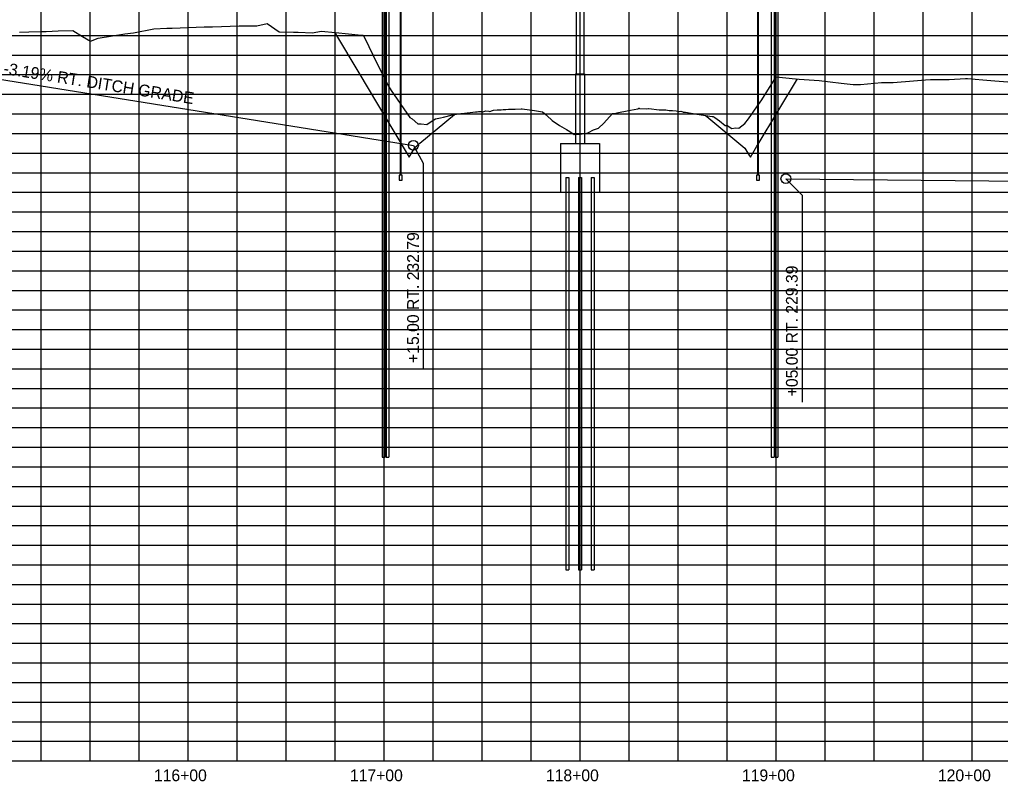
# Model space of a CAD drawing. Extents: x 921603 to 924670, y 1759276 to 1766491.
# Drawn here: x 923154 to 923654, y 1764922 to 1765310 of the extents above; entities that cross this region are included whole.
import ezdxf

# ---------------------------------------------------------------- set-up
doc = ezdxf.new("R2010")
doc.units = 0
for name, color, linetype in [('B-Gen-Hidden', 7, 'Continuous'), ('B-Gen-Object', 7, 'Continuous'), ('B-Sub-Retaining Wall', 7, 'Continuous'), ('R_Axis_Annotation', 7, 'Continuous'), ('R_Exist Surface', 7, 'Continuous'), ('R_Grid', 7, 'Continuous'), ('R_Grid_Minor', 7, 'Continuous'), ('R_Prop Surface', 7, 'Continuous'), ('R_Vert Alg', 7, 'Continuous'), ('R_Vert Alg Annot', 7, 'Continuous')]:
    doc.layers.add(name, color=color, linetype=linetype)

msp = doc.modelspace()

# ---------------------------------------------------------------- linework, layer by layer
at = {"layer": 'B-Gen-Hidden'}
for p, q in [((923338.85, 1765337.18), (923338.85, 1765087.18)), ((923340.35, 1765337.18), (923340.35, 1765087.18)), ((923340.85, 1765337.18), (923340.85, 1765087.18)), ((923342.35, 1765337.18), (923342.35, 1765087.18)), ((923537.3, 1765337.18), (923537.3, 1765087.18)), ((923538.8, 1765337.18), (923538.8, 1765087.18)), ((923539.3, 1765337.18), (923539.3, 1765087.18)), ((923540.8, 1765337.18), (923540.8, 1765087.18)), ((923437.58, 1765257.21), (923437.58, 1765247.23)), ((923442.08, 1765257.69), (923442.08, 1765247.23)), ((923429.83, 1765247.23), (923449.83, 1765247.23)), ((923429.83, 1765247.23), (923429.83, 1765222.23)), ((923449.83, 1765247.23), (923449.83, 1765222.23)), ((923432.58, 1765229.73), (923432.58, 1765029.73)), ((923432.58, 1765229.73), (923434.08, 1765229.73)), ((923434.08, 1765229.73), (923434.08, 1765029.73)), ((923439.08, 1765229.73), (923439.08, 1765029.73)), ((923439.08, 1765229.73), (923440.58, 1765229.73)), ((923440.58, 1765229.73), (923440.58, 1765029.73)), ((923445.58, 1765229.73), (923445.58, 1765029.73)), ((923445.58, 1765229.73), (923447.08, 1765229.73)), ((923447.08, 1765229.73), (923447.08, 1765029.73)), ((923449.83, 1765222.23), (923429.83, 1765222.23)), ((923338.85, 1765087.18), (923340.35, 1765087.18)), ((923340.85, 1765087.18), (923342.35, 1765087.18)), ((923537.3, 1765087.18), (923538.8, 1765087.18)), ((923539.3, 1765087.18), (923540.8, 1765087.18)), ((923432.58, 1765029.73), (923434.08, 1765029.73)), ((923439.08, 1765029.73), (923440.58, 1765029.73)), ((923445.58, 1765029.73), (923447.08, 1765029.73))]:
    msp.add_line(p, q, dxfattribs=at)
at = {"layer": 'B-Gen-Object'}
for p, q in [((923437.83, 1765330.16), (923437.83, 1765282.66)), ((923441.84, 1765330.16), (923441.84, 1765282.66)), ((923437.58, 1765282.66), (923437.58, 1765257.21)), ((923437.58, 1765282.66), (923442.08, 1765282.66)), ((923442.08, 1765282.66), (923442.08, 1765257.69))]:
    msp.add_line(p, q, dxfattribs=at)
at = {"layer": 'B-Sub-Retaining Wall'}
for p, q in [((923348.02, 1765334.08), (923348.02, 1765230.99)), ((923348.52, 1765230.99), (923348.52, 1765334.08)), ((923530.4, 1765334.08), (923530.4, 1765230.99)), ((923530.9, 1765230.99), (923530.9, 1765334.08)), ((923347.54, 1765230.99), (923347.54, 1765228.49)), ((923349, 1765230.99), (923347.54, 1765230.99)), ((923349, 1765228.49), (923349, 1765230.99)), ((923529.92, 1765230.99), (923529.92, 1765228.49)), ((923531.38, 1765230.99), (923529.92, 1765230.99)), ((923531.38, 1765228.49), (923531.38, 1765230.99)), ((923347.54, 1765228.49), (923349, 1765228.49)), ((923529.92, 1765228.49), (923531.38, 1765228.49))]:
    msp.add_line(p, q, dxfattribs=at)
at = {"layer": 'R_Exist Surface'}
msp.add_lwpolyline([(923153.87, 1765303.95), (923158.57, 1765304.12), (923164.55, 1765304.24), (923167.47, 1765304.31), (923173.49, 1765304.53), (923181.06, 1765304.72), (923186.05, 1765301.75), (923190.01, 1765299.41), (923194.03, 1765300.92), (923207.55, 1765303.15), (923207.56, 1765303.15), (923212.09, 1765303.63), (923222.44, 1765305.62), (923229.05, 1765305.89), (923230.22, 1765305.93), (923231.8, 1765305.97), (923248.12, 1765306.6), (923250.55, 1765306.66), (923252.29, 1765306.7), (923265.93, 1765307.21), (923272.06, 1765307.16), (923274.92, 1765307.15), (923280.21, 1765308.4), (923286.34, 1765304.18), (923293.56, 1765303.91), (923294.54, 1765303.87), (923296.01, 1765303.89), (923303.3, 1765303.62), (923307.83, 1765304.46), (923315.06, 1765303.73), (923328.41, 1765302.38), (923329.1, 1765302.36), (923329.11, 1765302.35), (923329.84, 1765301.29), (923336.52, 1765287.44), (923336.56, 1765287.37), (923342.02, 1765276.41), (923343.53, 1765274.17), (923353.01, 1765260.44), (923354.21, 1765259.73), (923357.1, 1765257.12), (923358.06, 1765257.13), (923358.77, 1765257.13), (923361.68, 1765256.82), (923363.86, 1765258.42), (923366.05, 1765259.77), (923368.67, 1765260.28), (923370.13, 1765260.63), (923374.8, 1765261.72), (923375.68, 1765262.01), (923379, 1765262.43), (923379.56, 1765262.5), (923386.51, 1765263.27), (923387.36, 1765263.37), (923387.94, 1765263.48), (923389.79, 1765263.52), (923390.25, 1765263.38), (923391.25, 1765263.65), (923391.76, 1765263.74), (923393.21, 1765263.57), (923393.76, 1765263.5), (923395.08, 1765263.9), (923395.67, 1765264.16), (923397.59, 1765264.36), (923398.48, 1765264.38), (923399.67, 1765264.3), (923400.57, 1765264.52), (923401.06, 1765264.46), (923401.32, 1765264.43), (923401.93, 1765264.54), (923403.35, 1765264.71), (923404.11, 1765264.59), (923406.25, 1765264.59), (923406.76, 1765264.59), (923409.73, 1765264.81), (923410.36, 1765264.75), (923410.36, 1765264.75), (923416.62, 1765263.91), (923420.65, 1765263.23), (923422.57, 1765261.76), (923422.96, 1765261.46), (923425.62, 1765258.92), (923429.35, 1765256.4), (923432.88, 1765254.23), (923434.62, 1765253.23), (923436.86, 1765251.78), (923439.72, 1765251.92), (923443.26, 1765252.48), (923444.07, 1765252.84), (923446.72, 1765254.04), (923449.29, 1765255.02), (923452.02, 1765257.55), (923456.38, 1765262.53), (923458.31, 1765262.69), (923458.74, 1765262.74), (923459.49, 1765262.89), (923463.93, 1765263.81), (923465.57, 1765264.15), (923469.28, 1765264.91), (923469.87, 1765265.09), (923469.95, 1765265.1), (923470.17, 1765265.08), (923473.66, 1765264.83), (923473.79, 1765264.85), (923474.72, 1765264.96), (923474.92, 1765264.93), (923480.16, 1765264.28), (923480.35, 1765264.27), (923483.38, 1765264.28), (923483.54, 1765264.26), (923485.26, 1765263.98), (923485.51, 1765263.97), (923487.07, 1765263.9), (923488.94, 1765263.81), (923490.29, 1765263.48), (923490.36, 1765263.47), (923491.33, 1765263.57), (923492.3, 1765263.22), (923492.38, 1765263.21), (923493.7, 1765263.08), (923493.71, 1765263.08), (923499.44, 1765262.17), (923507.28, 1765260.94), (923507.82, 1765260.84), (923508.05, 1765260.7), (923508.57, 1765260.34), (923511.04, 1765258.67), (923513.95, 1765256.28), (923515.12, 1765256.27), (923515.99, 1765255.71), (923517.3, 1765254.75), (923519.09, 1765255.06), (923520.92, 1765255), (923523.85, 1765257.35), (923525.74, 1765259.69), (923530.07, 1765265.88), (923532.59, 1765269.49), (923539.92, 1765281.15), (923549.68, 1765280.06), (923551.58, 1765279.95), (923561.75, 1765279.36), (923573.08, 1765277.93), (923579.21, 1765277.16), (923582.85, 1765277.17), (923593.6, 1765278.21), (923594.58, 1765278.21), (923599.66, 1765278.22), (923610.02, 1765279.05), (923616.08, 1765279.54), (923618.61, 1765279.75), (923628.16, 1765279.72), (923636.41, 1765280.3), (923637.58, 1765280.22), (923645.31, 1765279.68), (923651.49, 1765279.08), (923660.29, 1765278.47)], dxfattribs=at)
at = {"layer": 'R_Grid'}
for p, q in [((923239.83, 1764932.26), (923239.83, 1765532.26)), ((923339.83, 1764932.26), (923339.83, 1765532.26)), ((923439.83, 1764932.26), (923439.83, 1765532.26)), ((923539.83, 1764932.26), (923539.83, 1765532.26)), ((923639.83, 1764932.26), (923639.83, 1765532.26)), ((921639.83, 1765282.26), (924639.83, 1765282.26)), ((921639.83, 1765232.26), (924639.83, 1765232.26)), ((921639.83, 1765182.26), (924639.83, 1765182.26)), ((921639.83, 1765132.26), (924639.83, 1765132.26)), ((921639.83, 1765082.26), (924639.83, 1765082.26)), ((921639.83, 1765032.26), (924639.83, 1765032.26)), ((921639.83, 1764982.26), (924639.83, 1764982.26)), ((921639.83, 1764932.26), (924639.83, 1764932.26))]:
    msp.add_line(p, q, dxfattribs=at)
at = {"layer": 'R_Grid_Minor'}
for p, q in [((923164.83, 1764932.26), (923164.83, 1765532.26)), ((923189.83, 1764932.26), (923189.83, 1765532.26)), ((923214.83, 1764932.26), (923214.83, 1765532.26)), ((923264.83, 1764932.26), (923264.83, 1765532.26)), ((923289.83, 1764932.26), (923289.83, 1765532.26)), ((923314.83, 1764932.26), (923314.83, 1765532.26)), ((923364.83, 1764932.26), (923364.83, 1765532.26)), ((923389.83, 1764932.26), (923389.83, 1765532.26)), ((923414.83, 1764932.26), (923414.83, 1765532.26)), ((923464.83, 1764932.26), (923464.83, 1765532.26)), ((923489.83, 1764932.26), (923489.83, 1765532.26)), ((923514.83, 1764932.26), (923514.83, 1765532.26)), ((923564.83, 1764932.26), (923564.83, 1765532.26)), ((923589.83, 1764932.26), (923589.83, 1765532.26)), ((923614.83, 1764932.26), (923614.83, 1765532.26)), ((921639.83, 1765302.26), (924639.83, 1765302.26)), ((921639.83, 1765292.26), (924639.83, 1765292.26)), ((921639.83, 1765272.26), (924639.83, 1765272.26)), ((921639.83, 1765262.26), (924639.83, 1765262.26)), ((921639.83, 1765252.26), (924639.83, 1765252.26)), ((921639.83, 1765242.26), (924639.83, 1765242.26)), ((921639.83, 1765222.26), (924639.83, 1765222.26)), ((921639.83, 1765212.26), (924639.83, 1765212.26)), ((921639.83, 1765202.26), (924639.83, 1765202.26)), ((921639.83, 1765192.26), (924639.83, 1765192.26)), ((921639.83, 1765172.26), (924639.83, 1765172.26)), ((921639.83, 1765162.26), (924639.83, 1765162.26)), ((921639.83, 1765152.26), (924639.83, 1765152.26)), ((921639.83, 1765142.26), (924639.83, 1765142.26)), ((921639.83, 1765122.26), (924639.83, 1765122.26)), ((921639.83, 1765112.26), (924639.83, 1765112.26)), ((921639.83, 1765102.26), (924639.83, 1765102.26)), ((921639.83, 1765092.26), (924639.83, 1765092.26)), ((921639.83, 1765072.26), (924639.83, 1765072.26)), ((921639.83, 1765062.26), (924639.83, 1765062.26)), ((921639.83, 1765052.26), (924639.83, 1765052.26)), ((921639.83, 1765042.26), (924639.83, 1765042.26)), ((921639.83, 1765022.26), (924639.83, 1765022.26)), ((921639.83, 1765012.26), (924639.83, 1765012.26)), ((921639.83, 1765002.26), (924639.83, 1765002.26)), ((921639.83, 1764992.26), (924639.83, 1764992.26)), ((921639.83, 1764972.26), (924639.83, 1764972.26)), ((921639.83, 1764962.26), (924639.83, 1764962.26)), ((921639.83, 1764952.26), (924639.83, 1764952.26)), ((921639.83, 1764942.26), (924639.83, 1764942.26))]:
    msp.add_line(p, q, dxfattribs=at)
at = {"layer": 'R_Prop Surface'}
for points in [[(923314.61, 1765303.77), (923315.06, 1765303.03), (923326.99, 1765283.11), (923336.56, 1765267.14), (923352.68, 1765240.24), (923355.71, 1765245.29), (923355.73, 1765245.32), (923356.38, 1765245.87), (923358.06, 1765247.27), (923375.75, 1765262.02)], [(923503.89, 1765261.48), (923504.54, 1765260.93), (923508.57, 1765257.58), (923508.62, 1765257.54), (923523.9, 1765244.85), (923526.3, 1765240.85), (923526.71, 1765240.17), (923530.07, 1765245.77), (923530.69, 1765246.8), (923550.7, 1765280.06)]]:
    msp.add_lwpolyline(points, dxfattribs=at)
at = {"layer": 'R_Vert Alg'}
for p, q in [((923039.83, 1765296.51), (923354.83, 1765246.21)), ((923544.83, 1765229.21), (923902.83, 1765225.61))]:
    msp.add_line(p, q, dxfattribs=at)
at = {"layer": 'R_Vert Alg Annot'}
for p, q in [((923354.83, 1765246.21), (923359.87, 1765237.15)), ((923359.87, 1765237.15), (923359.87, 1765132.21)), ((923544.83, 1765229.21), (923553.13, 1765220.75)), ((923553.13, 1765220.75), (923553.13, 1765115.21))]:
    msp.add_line(p, q, dxfattribs=at)
for centre in [(923354.83, 1765246.21), (923544.83, 1765229.21)]:
    msp.add_circle(centre, 2.5, dxfattribs=at)

# ---------------------------------------------------------------- texts
at = {"layer": 'R_Axis_Annotation'}
for s, p in [('116+00', (923222.42, 1764921.91)), ('117+00', (923322.42, 1764921.91)), ('118+00', (923422.42, 1764921.91)), ('119+00', (923522.42, 1764921.91)), ('120+00', (923622.42, 1764921.91))]:
    msp.add_text(s, height=6, dxfattribs=at).set_placement(p)
at = {"layer": 'R_Vert Alg Annot'}
for s, rotation, p in [('-3.19% RT. DITCH GRADE', 350.9275, (923145.43, 1765282.66)), ('+15.00 RT. 232.79', 90, (923357.62, 1765135.21)), ('+05.00 RT. 229.39', 90, (923550.88, 1765118.21))]:
    msp.add_text(s, height=6, rotation=rotation, dxfattribs=at).set_placement(p)

doc.saveas('drawing.dxf')
